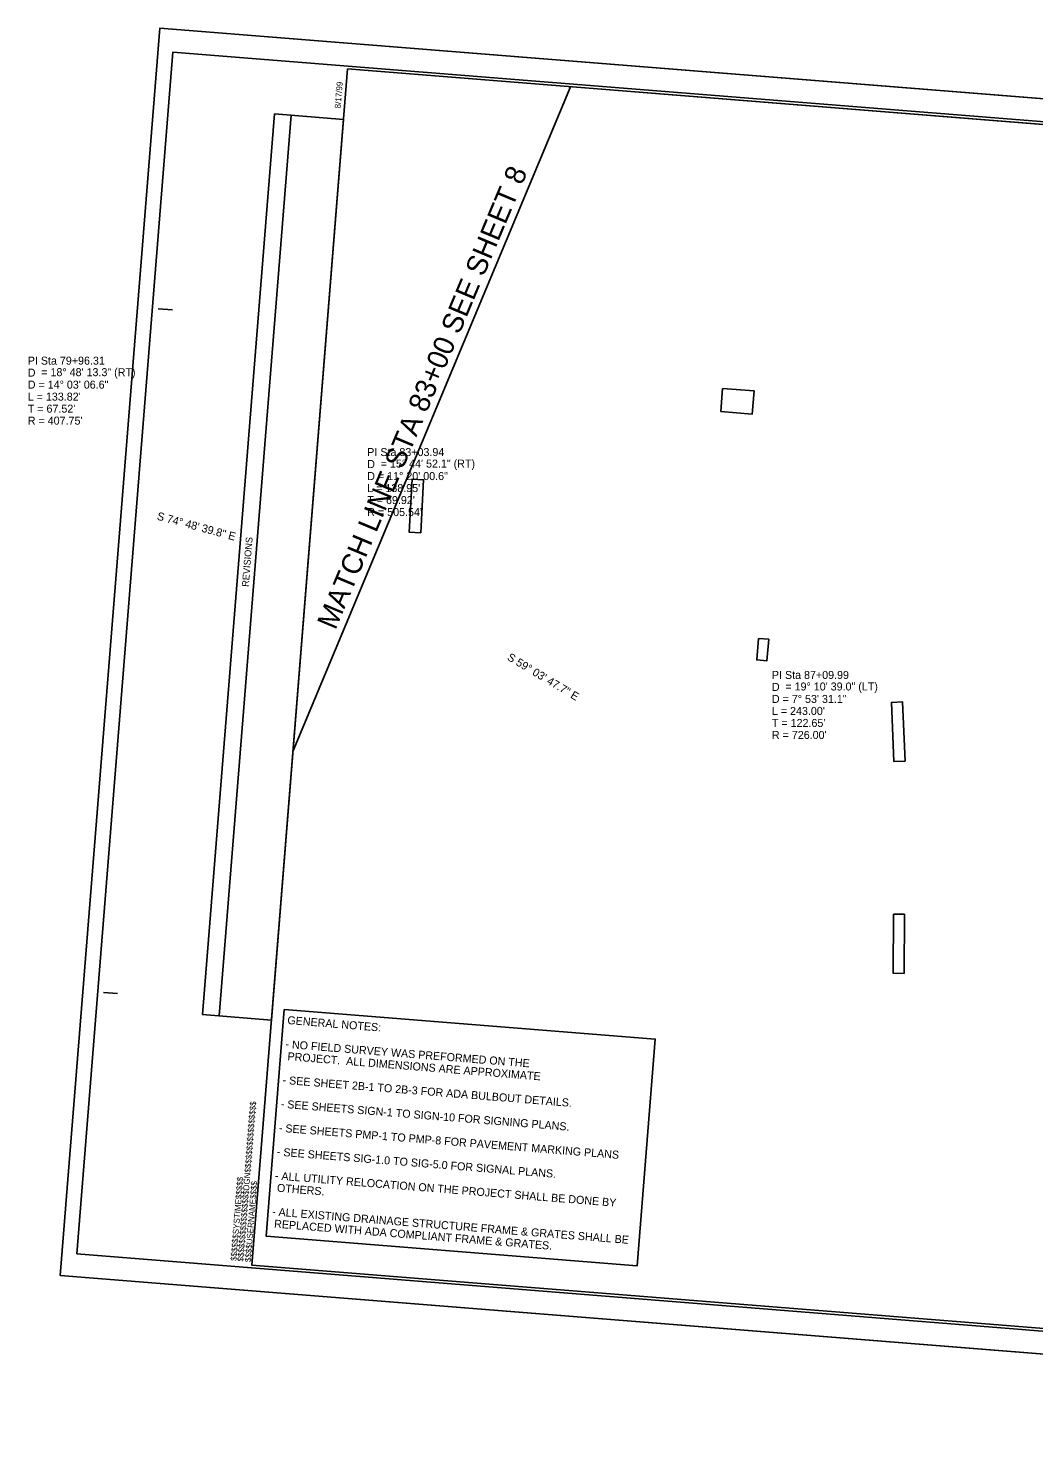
# Model space of a CAD drawing. Extents: x 928111 to 937215, y 683930 to 686530.
# Drawn here: x 934269 to 935149, y 683930 to 685156 of the extents above; entities that cross this region are included whole.
import ezdxf

# ---------------------------------------------------------------- set-up
doc = ezdxf.new("R2010")
doc.units = 0
for name, color, linetype in [('Exist Horizontal Alignment Curve and Spiral Data', 7, 'Continuous'), ('Exist Horizontal Alignment Direction Label', 7, 'Continuous'), ('Matchline', 7, 'Continuous'), ('Matchline Text', 7, 'Continuous'), ('Prop DSN Text', 7, 'Continuous'), ('Sheet Cutting Line CELL', 7, 'Continuous'), ('Sheet Layout Plan Border', 7, 'Continuous'), ('Sheet Plan CELL', 7, 'Continuous'), ('Sheet Plan Layout CELL', 7, 'Continuous'), ('Sheet Plot Border Inside CELL', 7, 'Continuous'), ('Sheet Plot Border Outside CELL', 7, 'Continuous')]:
    doc.layers.add(name, color=color, linetype=linetype)

msp = doc.modelspace()

# ---------------------------------------------------------------- linework, layer by layer
at = {"layer": 'Matchline'}
msp.add_line((934501, 684522.6), (934743.9, 685104.2), dxfattribs=at)
at = {"layer": 'Prop DSN Text'}
for points in [[(934876.9, 684840.2), (934904.4, 684838), (934902.8, 684817.8), (934875.3, 684820)], [(934613, 684713.8), (934615.3, 684760.3), (934605.2, 684760.9), (934602.8, 684714.3)], [(934908.2, 684621.4), (934906.7, 684602.6), (934915.7, 684601.9), (934917.2, 684620.7)], [(935036.5, 684514.1), (935034.2, 684566), (935024.5, 684565.5), (935026.8, 684513.7)], [(935026.3, 684380.2), (935026.1, 684328.5), (935035.7, 684328.4), (935035.9, 684380.1)], [(934493.3, 684296.8), (934818, 684270.9), (934802.1, 684072.5), (934477.5, 684098.5)]]:
    msp.add_lwpolyline(points, close=True, dxfattribs=at)
at = {"layer": 'Sheet Cutting Line CELL'}
for p, q in [((934384.6, 685155.5), (934297.3, 684064)), ((936062.7, 685021.3), (934384.6, 685155.5)), ((934297.3, 684064), (935975.4, 683929.8))]:
    msp.add_line(p, q, dxfattribs=at)
at = {"layer": 'Sheet Layout Plan Border'}
msp.add_line((934501, 684522.6), (934743.9, 685104.2), dxfattribs=at)
at = {"layer": 'Sheet Plan CELL'}
for p, q in [((934548.8, 685119.8), (934548.8, 685119.8)), ((934436.4, 684291.1), (934499.4, 685079.3)), ((934383, 684909.8), (934395.5, 684908.9)), ((934335.2, 684311.8), (934347.6, 684310.8)), ((934465, 684073.2), (934465, 684073.2))]:
    msp.add_line(p, q, dxfattribs=at)
for points in [[(936044, 685000.2), (934548.8, 685119.8), (934465, 684073.2), (935960.3, 683953.6)], [(934421.8, 684292.3), (934484.9, 685080.4), (934545.2, 685075.6), (934482.2, 684287.5)]]:
    msp.add_lwpolyline(points, close=True, dxfattribs=at)
at = {"layer": 'Sheet Plan Layout CELL'}
msp.add_lwpolyline([(934548.7, 685119.8), (934465, 684073.2), (935960.3, 683953.6), (936027.1, 684789.4), (935788.6, 684808.5), (935805.5, 685019.3)], close=True, dxfattribs=at)
at = {"layer": 'Sheet Plot Border Inside CELL'}
msp.add_lwpolyline([(934311.8, 684082.9), (935972.5, 683950.1), (936056.7, 685001.7), (934396, 685134.5)], close=True, dxfattribs=at)
at = {"layer": 'Sheet Plot Border Outside CELL'}
msp.add_lwpolyline([(934297.3, 684064), (935975.4, 683929.8), (936062.7, 685021.3), (934384.6, 685155.5)], close=True, dxfattribs=at)

# ---------------------------------------------------------------- texts
at = {"layer": 'Exist Horizontal Alignment Curve and Spiral Data'}
for s, p in [('PI Sta 79+96.31', (934269, 684861)), ('D', (934269, 684850.5)), ('= 18%%d 48\' 13.3" (RT)', (934280.8, 684850.9)), ('D = 14%%d 03\' 06.6"', (934269, 684840)), ("L = 133.82'", (934269, 684829.5)), ("T = 67.52'", (934269, 684819)), ("R = 407.75'", (934269, 684808.5)), ('PI Sta 83+03.94', (934566, 684781)), ('D', (934566, 684770.5)), ('= 15%%d 44\' 52.1" (RT)', (934577.8, 684770.9)), ('D = 11%%d 20\' 00.6"', (934566, 684760)), ("L = 138.95'", (934566, 684749.5)), ("T = 69.92'", (934566, 684739)), ("R = 505.54'", (934566, 684728.5)), ('PI Sta 87+09.99', (934920, 684586)), ('D', (934920, 684575.5)), ('= 19%%d 10\' 39.0" (LT)', (934931.8, 684575.9)), ('D = 7%%d 53\' 31.1"', (934920, 684565)), ("L = 243.00'", (934920, 684554.5)), ("T = 122.65'", (934920, 684544)), ("R = 726.00'", (934920, 684533.5))]:
    msp.add_text(s, height=7, dxfattribs=at).set_placement(p)
at = {"layer": 'Exist Horizontal Alignment Direction Label'}
for s, rotation, p in [('S 74%%d 48\' 39.8" E', 344.8111, (934381.5, 684725.5)), ('S 59%%d 03\' 47.7" E', 329.0633, (934687.8, 684603.1))]:
    msp.add_text(s, height=7, rotation=rotation, dxfattribs=at).set_placement(p)
at = {"layer": 'Matchline Text'}
msp.add_text('MATCH LINE STA 83+00 SEE SHEET 8 ', height=18, rotation=67.2535, dxfattribs=at).set_placement((934538.1, 684628.2))
at = {"layer": 'Prop DSN Text'}
for s, p in [('GENERAL NOTES:', (934495.9, 684284.1)), ('- NO FIELD SURVEY WAS PREFORMED ON THE ', (934494.2, 684263.2)), (' PROJECT.  ALL DIMENSIONS ARE APPROXIMATE', (934493.4, 684252.7)), ('- SEE SHEET 2B-1 TO 2B-3 FOR ADA BULBOUT DETAILS.', (934491.7, 684231.8)), ('- SEE SHEETS SIGN-1 TO SIGN-10 FOR SIGNING PLANS.', (934490.1, 684210.9)), ('- SEE SHEETS PMP-1 TO PMP-8 FOR PAVEMENT MARKING PLANS  ', (934488.4, 684189.9)), ('- SEE SHEETS SIG-1.0 TO SIG-5.0 FOR SIGNAL PLANS.', (934486.7, 684169)), ('- ALL UTILITY RELOCATION ON THE PROJECT SHALL BE DONE BY ', (934485, 684148.1)), (' OTHERS.', (934484.2, 684137.6)), ('- ALL EXISTING DRAINAGE STRUCTURE FRAME & GRATES SHALL BE ', (934482.5, 684116.7)), (' REPLACED WITH ADA COMPLIANT FRAME & GRATES.', (934481.7, 684106.2))]:
    msp.add_text(s, height=7, rotation=355.4267, dxfattribs=at).set_placement(p)
at = {"layer": 'Sheet Plan CELL'}
for s, height, rotation, p in [('8/17/99', 5.25, 85.4268, (934542.7, 685085)), ('REVISIONS', 6, 85.4267, (934462.3, 684666.4)), ('$$$$$$$$$$$$$$$$DGN$$$$$$$$$$$$$$$$', 5.25, 85.4268, (934457.6, 684076.1)), ('$$$$$$SYSTIME$$$$$', 5.25, 85.4268, (934451.6, 684076.6)), ('$$$$USERNAME$$$$', 5.25, 85.4268, (934464.1, 684075.6))]:
    msp.add_text(s, height=height, rotation=rotation, dxfattribs=at).set_placement(p)

doc.saveas('drawing.dxf')
